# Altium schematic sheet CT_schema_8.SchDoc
size 254 x 194 mm
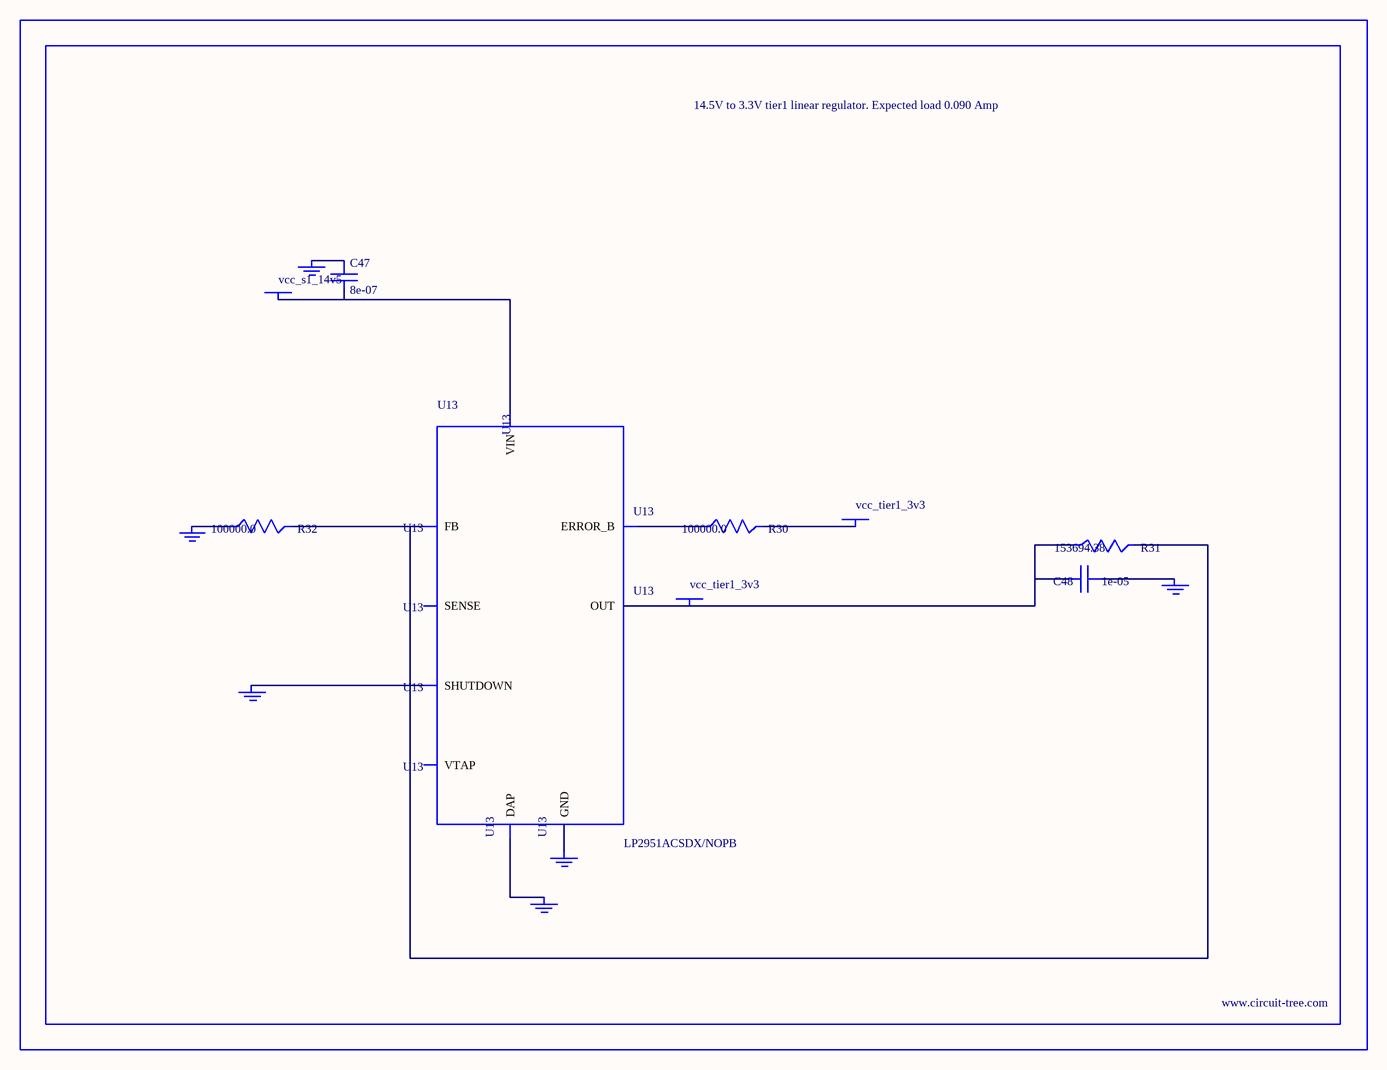
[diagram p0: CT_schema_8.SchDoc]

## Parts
BORDER7  (no value)
C47  8e-07  [R0603]
C48  1e-05  [C1210]
GND_INSTANCE_7_0  (no value)
GND_INSTANCE_7_1  (no value)
GND_INSTANCE_7_2  (no value)
GND_INSTANCE_7_3  (no value)
GND_INSTANCE_7_4  (no value)
GND_INSTANCE_7_5  (no value)
POWER_INSTANCE_7_0  vcc_tier1_3v3
POWER_INSTANCE_7_1  vcc_s1_14v5
POWER_INSTANCE_7_2  vcc_tier1_3v3
R30  100000.0  [R0603]
R31  153694.38  [R0603]
R32  100000.0  [R0603]
U13  LP2951ACSDX/NOPB  [WSON-8]

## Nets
NetC47_1: C47.1 GND_INSTANCE_7_3.0(GND)
NetC47_2: C47.2 POWER_INSTANCE_7_1.0(PWR) U13.8(VIN)
NetC48_1: C48.1 GND_INSTANCE_7_0.0(GND)
NetC48_2: C48.2 POWER_INSTANCE_7_2.0(PWR) R31.1 U13.1(OUT)
NetGND_INSTANCE_7_1_0: GND_INSTANCE_7_1.0(GND) U13.3(SHUTDOWN)
NetGND_INSTANCE_7_2_0: GND_INSTANCE_7_2.0(GND) R32.1
NetGND_INSTANCE_7_4_0: GND_INSTANCE_7_4.0(GND) U13.PAD(DAP)
NetGND_INSTANCE_7_5_0: GND_INSTANCE_7_5.0(GND) U13.4(GND)
NetPOWER_INSTANCE_7_0_0: POWER_INSTANCE_7_0.0(PWR) R30.2
NetR30_1: R30.1 U13.5(ERROR_B)
NetR31_2: R31.2 R32.2 U13.7(FB)

Not connected (* = marked no-connect by the designer): U13 2(SENSE) 6(VTAP)

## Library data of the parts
BORDER7 = BORDER_PAGE7
C47 = C47
C48 = GRM32DR61E106MA12L
GND_INSTANCE_7_0-GND_INSTANCE_7_5 = GND
POWER_INSTANCE_7_0-POWER_INSTANCE_7_2 = PWR
R30 R32 = RC0603JR-07100KL
R31 = R31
